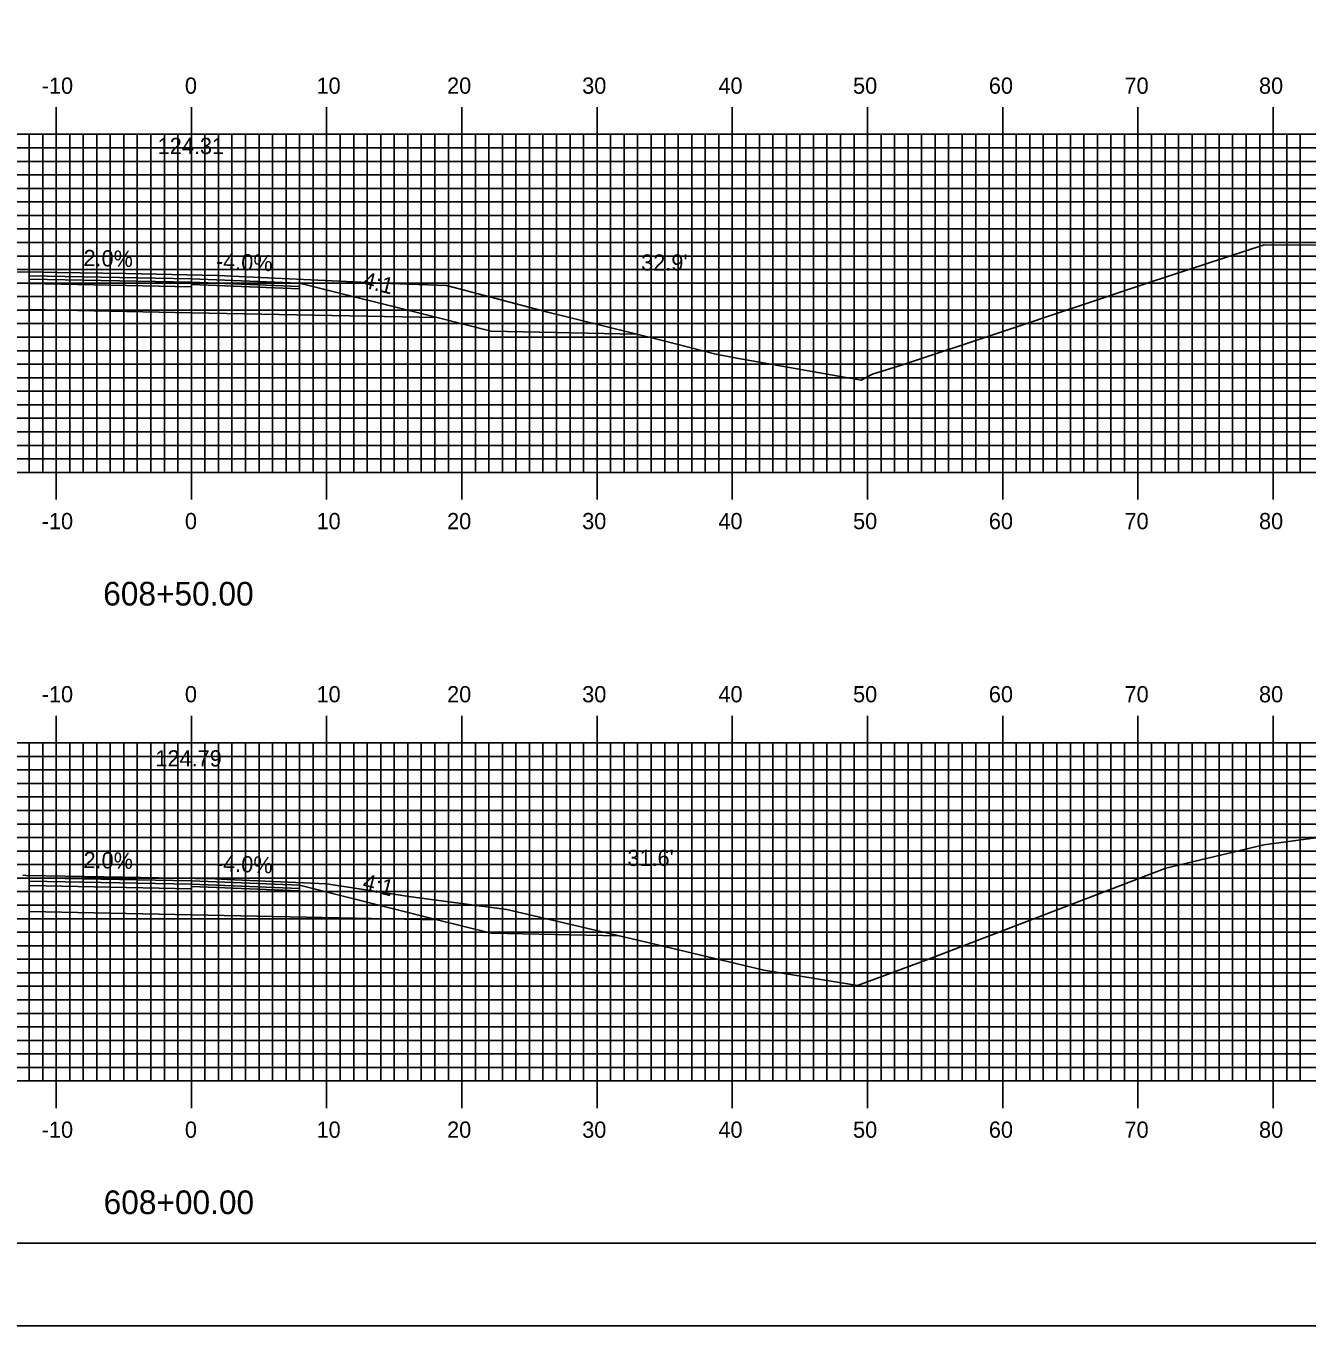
# Model space of a CAD drawing. Extents: x 842962 to 843305, y 363538 to 363758.
# Drawn here: x 843115.7 to 843210.4, y 363537.6 to 363633.7 of the extents above; entities that cross this region are included whole.
import ezdxf

# ---------------------------------------------------------------- set-up
doc = ezdxf.new("R2010")
doc.units = 0
for name, color, linetype in [('ANNOTATION', 7, 'Continuous'), ('BORDER', 7, 'Continuous'), ('D_Roadway_Centerline', 7, 'Continuous'), ('D_Roadway_Centerline_Text', 7, 'Continuous'), ('D_Roadway_Edge_Shoulder', 7, 'Continuous'), ('D_Roadway_Edge_TW', 7, 'Continuous'), ('D_Roadway_FinishedGrade', 7, 'Continuous'), ('D_Roadway_Pavement', 7, 'Continuous'), ('D_Roadway_SubGrade', 7, 'Continuous'), ('D_Text_Standard', 7, 'Continuous'), ('H_V ANNOTATION', 7, 'Continuous'), ('M_Roadway_Centerline', 7, 'Continuous'), ('MAJOR', 7, 'Continuous'), ('MINOR', 7, 'Continuous'), ('PLOT BOUNDARY', 7, 'Continuous'), ('S_Roadway_Centerline', 7, 'Continuous')]:
    doc.layers.add(name, color=color, linetype=linetype)

msp = doc.modelspace()

# ---------------------------------------------------------------- linework, layer by layer
at = {"layer": 'BORDER'}
msp.add_lwpolyline([(842978.311, 363543.721), (843298.311, 363543.721), (843298.311, 363753.721), (842978.311, 363753.721)], close=True, dxfattribs=at)
at = {"layer": 'D_Roadway_Centerline'}
msp.add_lwpolyline([(843115.911, 363570.752), (843127.911, 363570.512), (843135.911, 363570.192), (843146.085, 363567.648)], dxfattribs=at)
at = {"layer": 'D_Roadway_Edge_Shoulder'}
for p, q in [((843115.911, 363615.017), (843115.911, 363615.267)), ((843115.911, 363570.502), (843115.911, 363570.752))]:
    msp.add_line(p, q, dxfattribs=at)
for points in [[(843127.911, 363615.027), (843135.911, 363614.707), (843135.911, 363614.457), (843127.911, 363614.777)], [(843127.911, 363570.512), (843135.911, 363570.192), (843135.911, 363569.942), (843127.911, 363570.262)]]:
    msp.add_lwpolyline(points, close=True, dxfattribs=at)
at = {"layer": 'D_Roadway_Edge_TW'}
for points in [[(843115.911, 363615.267), (843127.911, 363615.027), (843127.911, 363614.777), (843115.911, 363615.017)], [(843115.911, 363570.752), (843127.911, 363570.512), (843127.911, 363570.262), (843115.911, 363570.502)]]:
    msp.add_lwpolyline(points, close=True, dxfattribs=at)
at = {"layer": 'D_Roadway_FinishedGrade'}
for points in [[(843146.085, 363612.163), (843150.085, 363611.163), (843160.782, 363610.949)], [(843146.085, 363567.648), (843150.085, 363566.648), (843159.503, 363566.46)]]:
    msp.add_lwpolyline(points, dxfattribs=at)
at = {"layer": 'D_Roadway_Pavement'}
for p, q in [((843115.911, 363614.683), (843115.911, 363615.017)), ((843115.911, 363570.168), (843115.911, 363570.502))]:
    msp.add_line(p, q, dxfattribs=at)
for points in [[(843115.911, 363615.017), (843127.911, 363614.777), (843127.911, 363614.443), (843115.911, 363614.683)], [(843127.911, 363614.777), (843135.911, 363614.457), (843135.911, 363614.29), (843127.911, 363614.61)], [(843115.911, 363570.502), (843127.911, 363570.262), (843127.911, 363569.928), (843115.911, 363570.168)], [(843127.911, 363570.262), (843135.911, 363569.942), (843135.911, 363569.775), (843127.911, 363570.095)]]:
    msp.add_lwpolyline(points, close=True, dxfattribs=at)
for points in [[(843127.911, 363614.777), (843127.911, 363614.443)], [(843127.911, 363614.777), (843127.911, 363614.443)], [(843127.911, 363570.262), (843127.911, 363569.928)], [(843127.911, 363570.262), (843127.911, 363569.928)]]:
    msp.add_lwpolyline(points, dxfattribs=at)
at = {"layer": 'D_Roadway_SubGrade'}
for p, q in [((843115.911, 363623.864), (843115.911, 363612.767)), ((843115.911, 363612.767), (843115.911, 363614.683)), ((843115.911, 363579.349), (843115.911, 363568.252)), ((843115.911, 363568.252), (843115.911, 363570.168))]:
    msp.add_line(p, q, dxfattribs=at)
for points in [[(843115.911, 363614.683), (843127.911, 363614.443), (843127.911, 363612.527), (843115.911, 363612.767)], [(843127.911, 363614.443), (843127.911, 363614.777), (843135.911, 363614.457), (843135.911, 363614.707), (843146.085, 363612.163), (843127.911, 363612.527)], [(843115.911, 363570.168), (843127.911, 363569.928), (843127.911, 363568.012), (843115.911, 363568.252)], [(843127.911, 363569.928), (843127.911, 363570.262), (843135.911, 363569.942), (843135.911, 363570.192), (843146.085, 363567.648), (843127.911, 363568.012)]]:
    msp.add_lwpolyline(points, close=True, dxfattribs=at)
at = {"layer": 'MAJOR'}
for p, q in [((843117.911, 363627.725), (843117.911, 363625.721)), ((843127.911, 363627.725), (843127.911, 363625.721)), ((843137.911, 363627.725), (843137.911, 363625.721)), ((843147.911, 363627.725), (843147.911, 363625.721)), ((843157.911, 363627.725), (843157.911, 363625.721)), ((843167.911, 363627.725), (843167.911, 363625.721)), ((843177.911, 363627.725), (843177.911, 363625.721)), ((843187.911, 363627.725), (843187.911, 363625.721)), ((843197.911, 363627.725), (843197.911, 363625.721)), ((843207.911, 363627.725), (843207.911, 363625.721)), ((842987.911, 363625.721), (843267.911, 363625.721)), ((842987.911, 363625.721), (843267.911, 363625.721)), ((843117.911, 363600.721), (843117.911, 363625.721)), ((843127.911, 363600.721), (843127.911, 363625.721)), ((843137.911, 363600.721), (843137.911, 363625.721)), ((843147.911, 363600.721), (843147.911, 363625.721)), ((843157.911, 363600.721), (843157.911, 363625.721)), ((843167.911, 363600.721), (843167.911, 363625.721)), ((843177.911, 363600.721), (843177.911, 363625.721)), ((843187.911, 363600.721), (843187.911, 363625.721)), ((843197.911, 363600.721), (843197.911, 363625.721)), ((843207.911, 363600.721), (843207.911, 363625.721)), ((842987.911, 363620.721), (843267.911, 363620.721)), ((842987.911, 363615.721), (843267.911, 363615.721)), ((842987.911, 363610.721), (843267.911, 363610.721)), ((842987.911, 363605.721), (843267.911, 363605.721)), ((842987.911, 363600.721), (843267.911, 363600.721)), ((842987.911, 363600.721), (843267.911, 363600.721)), ((843117.911, 363598.717), (843117.911, 363600.721)), ((843127.911, 363598.717), (843127.911, 363600.721)), ((843137.911, 363598.717), (843137.911, 363600.721)), ((843147.911, 363598.717), (843147.911, 363600.721)), ((843157.911, 363598.717), (843157.911, 363600.721)), ((843167.911, 363598.717), (843167.911, 363600.721)), ((843177.911, 363598.717), (843177.911, 363600.721)), ((843187.911, 363598.717), (843187.911, 363600.721)), ((843197.911, 363598.717), (843197.911, 363600.721)), ((843207.911, 363598.717), (843207.911, 363600.721)), ((843117.911, 363582.725), (843117.911, 363580.721)), ((843127.911, 363582.725), (843127.911, 363580.721)), ((843137.911, 363582.725), (843137.911, 363580.721)), ((843147.911, 363582.725), (843147.911, 363580.721)), ((843157.911, 363582.725), (843157.911, 363580.721)), ((843167.911, 363582.725), (843167.911, 363580.721)), ((843177.911, 363582.725), (843177.911, 363580.721)), ((843187.911, 363582.725), (843187.911, 363580.721)), ((843197.911, 363582.725), (843197.911, 363580.721)), ((843207.911, 363582.725), (843207.911, 363580.721)), ((842987.911, 363580.721), (843267.911, 363580.721)), ((842987.911, 363580.721), (843267.911, 363580.721)), ((843117.911, 363555.721), (843117.911, 363580.721)), ((843127.911, 363555.721), (843127.911, 363580.721)), ((843137.911, 363555.721), (843137.911, 363580.721)), ((843147.911, 363555.721), (843147.911, 363580.721)), ((843157.911, 363555.721), (843157.911, 363580.721)), ((843167.911, 363555.721), (843167.911, 363580.721)), ((843177.911, 363555.721), (843177.911, 363580.721)), ((843187.911, 363555.721), (843187.911, 363580.721)), ((843197.911, 363555.721), (843197.911, 363580.721)), ((843207.911, 363555.721), (843207.911, 363580.721)), ((842987.911, 363575.721), (843267.911, 363575.721)), ((842987.911, 363570.721), (843267.911, 363570.721)), ((842987.911, 363565.721), (843267.911, 363565.721)), ((842987.911, 363560.721), (843267.911, 363560.721)), ((842987.911, 363555.721), (843267.911, 363555.721)), ((842987.911, 363555.721), (843267.911, 363555.721)), ((843117.911, 363553.717), (843117.911, 363555.721)), ((843127.911, 363553.717), (843127.911, 363555.721)), ((843137.911, 363553.717), (843137.911, 363555.721)), ((843147.911, 363553.717), (843147.911, 363555.721)), ((843157.911, 363553.717), (843157.911, 363555.721)), ((843167.911, 363553.717), (843167.911, 363555.721)), ((843177.911, 363553.717), (843177.911, 363555.721)), ((843187.911, 363553.717), (843187.911, 363555.721)), ((843197.911, 363553.717), (843197.911, 363555.721)), ((843207.911, 363553.717), (843207.911, 363555.721))]:
    msp.add_line(p, q, dxfattribs=at)
at = {"layer": 'MINOR'}
for p, q in [((843115.911, 363600.721), (843115.911, 363625.721)), ((843116.911, 363600.721), (843116.911, 363625.721)), ((843118.911, 363600.721), (843118.911, 363625.721)), ((843119.911, 363600.721), (843119.911, 363625.721)), ((843120.911, 363600.721), (843120.911, 363625.721)), ((843121.911, 363600.721), (843121.911, 363625.721)), ((843122.911, 363600.721), (843122.911, 363625.721)), ((843123.911, 363600.721), (843123.911, 363625.721)), ((843124.911, 363600.721), (843124.911, 363625.721)), ((843125.911, 363600.721), (843125.911, 363625.721)), ((843126.911, 363600.721), (843126.911, 363625.721)), ((843128.911, 363600.721), (843128.911, 363625.721)), ((843129.911, 363600.721), (843129.911, 363625.721)), ((843130.911, 363600.721), (843130.911, 363625.721)), ((843131.911, 363600.721), (843131.911, 363625.721)), ((843132.911, 363600.721), (843132.911, 363625.721)), ((843133.911, 363600.721), (843133.911, 363625.721)), ((843134.911, 363600.721), (843134.911, 363625.721)), ((843135.911, 363600.721), (843135.911, 363625.721)), ((843136.911, 363600.721), (843136.911, 363625.721)), ((843138.911, 363600.721), (843138.911, 363625.721)), ((843139.911, 363600.721), (843139.911, 363625.721)), ((843140.911, 363600.721), (843140.911, 363625.721)), ((843141.911, 363600.721), (843141.911, 363625.721)), ((843142.911, 363600.721), (843142.911, 363625.721)), ((843143.911, 363600.721), (843143.911, 363625.721)), ((843144.911, 363600.721), (843144.911, 363625.721)), ((843145.911, 363600.721), (843145.911, 363625.721)), ((843146.911, 363600.721), (843146.911, 363625.721)), ((843148.911, 363600.721), (843148.911, 363625.721)), ((843149.911, 363600.721), (843149.911, 363625.721)), ((843150.911, 363600.721), (843150.911, 363625.721)), ((843151.911, 363600.721), (843151.911, 363625.721)), ((843152.911, 363600.721), (843152.911, 363625.721)), ((843153.911, 363600.721), (843153.911, 363625.721)), ((843154.911, 363600.721), (843154.911, 363625.721)), ((843155.911, 363600.721), (843155.911, 363625.721)), ((843156.911, 363600.721), (843156.911, 363625.721)), ((843158.911, 363600.721), (843158.911, 363625.721)), ((843159.911, 363600.721), (843159.911, 363625.721)), ((843160.911, 363600.721), (843160.911, 363625.721)), ((843161.911, 363600.721), (843161.911, 363625.721)), ((843162.911, 363600.721), (843162.911, 363625.721)), ((843163.911, 363600.721), (843163.911, 363625.721)), ((843164.911, 363600.721), (843164.911, 363625.721)), ((843165.911, 363600.721), (843165.911, 363625.721)), ((843166.911, 363600.721), (843166.911, 363625.721)), ((843168.911, 363600.721), (843168.911, 363625.721)), ((843169.911, 363600.721), (843169.911, 363625.721)), ((843170.911, 363600.721), (843170.911, 363625.721)), ((843171.911, 363600.721), (843171.911, 363625.721)), ((843172.911, 363600.721), (843172.911, 363625.721)), ((843173.911, 363600.721), (843173.911, 363625.721)), ((843174.911, 363600.721), (843174.911, 363625.721)), ((843175.911, 363600.721), (843175.911, 363625.721)), ((843176.911, 363600.721), (843176.911, 363625.721)), ((843178.911, 363600.721), (843178.911, 363625.721)), ((843179.911, 363600.721), (843179.911, 363625.721)), ((843180.911, 363600.721), (843180.911, 363625.721)), ((843181.911, 363600.721), (843181.911, 363625.721)), ((843182.911, 363600.721), (843182.911, 363625.721)), ((843183.911, 363600.721), (843183.911, 363625.721)), ((843184.911, 363600.721), (843184.911, 363625.721)), ((843185.911, 363600.721), (843185.911, 363625.721)), ((843186.911, 363600.721), (843186.911, 363625.721)), ((843188.911, 363600.721), (843188.911, 363625.721)), ((843189.911, 363600.721), (843189.911, 363625.721)), ((843190.911, 363600.721), (843190.911, 363625.721)), ((843191.911, 363600.721), (843191.911, 363625.721)), ((843192.911, 363600.721), (843192.911, 363625.721)), ((843193.911, 363600.721), (843193.911, 363625.721)), ((843194.911, 363600.721), (843194.911, 363625.721)), ((843195.911, 363600.721), (843195.911, 363625.721)), ((843196.911, 363600.721), (843196.911, 363625.721)), ((843198.911, 363600.721), (843198.911, 363625.721)), ((843199.911, 363600.721), (843199.911, 363625.721)), ((843200.911, 363600.721), (843200.911, 363625.721)), ((843201.911, 363600.721), (843201.911, 363625.721)), ((843202.911, 363600.721), (843202.911, 363625.721)), ((843203.911, 363600.721), (843203.911, 363625.721)), ((843204.911, 363600.721), (843204.911, 363625.721)), ((843205.911, 363600.721), (843205.911, 363625.721)), ((843206.911, 363600.721), (843206.911, 363625.721)), ((843208.911, 363600.721), (843208.911, 363625.721)), ((843209.911, 363600.721), (843209.911, 363625.721)), ((842987.911, 363624.721), (843267.911, 363624.721)), ((842987.911, 363623.721), (843267.911, 363623.721)), ((842987.911, 363622.721), (843267.911, 363622.721)), ((842987.911, 363621.721), (843267.911, 363621.721)), ((842987.911, 363619.721), (843267.911, 363619.721)), ((842987.911, 363618.721), (843267.911, 363618.721)), ((842987.911, 363617.721), (843267.911, 363617.721)), ((842987.911, 363616.721), (843267.911, 363616.721)), ((842987.911, 363614.721), (843267.911, 363614.721)), ((842987.911, 363613.721), (843267.911, 363613.721)), ((842987.911, 363612.721), (843267.911, 363612.721)), ((842987.911, 363611.721), (843267.911, 363611.721)), ((842987.911, 363609.721), (843267.911, 363609.721)), ((842987.911, 363608.721), (843267.911, 363608.721)), ((842987.911, 363607.721), (843267.911, 363607.721)), ((842987.911, 363606.721), (843267.911, 363606.721)), ((842987.911, 363604.721), (843267.911, 363604.721)), ((842987.911, 363603.721), (843267.911, 363603.721)), ((842987.911, 363602.721), (843267.911, 363602.721)), ((842987.911, 363601.721), (843267.911, 363601.721)), ((843115.911, 363555.721), (843115.911, 363580.721)), ((843116.911, 363555.721), (843116.911, 363580.721)), ((843118.911, 363555.721), (843118.911, 363580.721)), ((843119.911, 363555.721), (843119.911, 363580.721)), ((843120.911, 363555.721), (843120.911, 363580.721)), ((843121.911, 363555.721), (843121.911, 363580.721)), ((843122.911, 363555.721), (843122.911, 363580.721)), ((843123.911, 363555.721), (843123.911, 363580.721)), ((843124.911, 363555.721), (843124.911, 363580.721)), ((843125.911, 363555.721), (843125.911, 363580.721)), ((843126.911, 363555.721), (843126.911, 363580.721)), ((843128.911, 363555.721), (843128.911, 363580.721)), ((843129.911, 363555.721), (843129.911, 363580.721)), ((843130.911, 363555.721), (843130.911, 363580.721)), ((843131.911, 363555.721), (843131.911, 363580.721)), ((843132.911, 363555.721), (843132.911, 363580.721)), ((843133.911, 363555.721), (843133.911, 363580.721)), ((843134.911, 363555.721), (843134.911, 363580.721)), ((843135.911, 363555.721), (843135.911, 363580.721)), ((843136.911, 363555.721), (843136.911, 363580.721)), ((843138.911, 363555.721), (843138.911, 363580.721)), ((843139.911, 363555.721), (843139.911, 363580.721)), ((843140.911, 363555.721), (843140.911, 363580.721)), ((843141.911, 363555.721), (843141.911, 363580.721)), ((843142.911, 363555.721), (843142.911, 363580.721)), ((843143.911, 363555.721), (843143.911, 363580.721)), ((843144.911, 363555.721), (843144.911, 363580.721)), ((843145.911, 363555.721), (843145.911, 363580.721)), ((843146.911, 363555.721), (843146.911, 363580.721)), ((843148.911, 363555.721), (843148.911, 363580.721)), ((843149.911, 363555.721), (843149.911, 363580.721)), ((843150.911, 363555.721), (843150.911, 363580.721)), ((843151.911, 363555.721), (843151.911, 363580.721)), ((843152.911, 363555.721), (843152.911, 363580.721)), ((843153.911, 363555.721), (843153.911, 363580.721)), ((843154.911, 363555.721), (843154.911, 363580.721)), ((843155.911, 363555.721), (843155.911, 363580.721)), ((843156.911, 363555.721), (843156.911, 363580.721)), ((843158.911, 363555.721), (843158.911, 363580.721)), ((843159.911, 363555.721), (843159.911, 363580.721)), ((843160.911, 363555.721), (843160.911, 363580.721)), ((843161.911, 363555.721), (843161.911, 363580.721)), ((843162.911, 363555.721), (843162.911, 363580.721)), ((843163.911, 363555.721), (843163.911, 363580.721)), ((843164.911, 363555.721), (843164.911, 363580.721)), ((843165.911, 363555.721), (843165.911, 363580.721)), ((843166.911, 363555.721), (843166.911, 363580.721)), ((843168.911, 363555.721), (843168.911, 363580.721)), ((843169.911, 363555.721), (843169.911, 363580.721)), ((843170.911, 363555.721), (843170.911, 363580.721)), ((843171.911, 363555.721), (843171.911, 363580.721)), ((843172.911, 363555.721), (843172.911, 363580.721)), ((843173.911, 363555.721), (843173.911, 363580.721)), ((843174.911, 363555.721), (843174.911, 363580.721)), ((843175.911, 363555.721), (843175.911, 363580.721)), ((843176.911, 363555.721), (843176.911, 363580.721)), ((843178.911, 363555.721), (843178.911, 363580.721)), ((843179.911, 363555.721), (843179.911, 363580.721)), ((843180.911, 363555.721), (843180.911, 363580.721)), ((843181.911, 363555.721), (843181.911, 363580.721)), ((843182.911, 363555.721), (843182.911, 363580.721)), ((843183.911, 363555.721), (843183.911, 363580.721)), ((843184.911, 363555.721), (843184.911, 363580.721)), ((843185.911, 363555.721), (843185.911, 363580.721)), ((843186.911, 363555.721), (843186.911, 363580.721)), ((843188.911, 363555.721), (843188.911, 363580.721)), ((843189.911, 363555.721), (843189.911, 363580.721)), ((843190.911, 363555.721), (843190.911, 363580.721)), ((843191.911, 363555.721), (843191.911, 363580.721)), ((843192.911, 363555.721), (843192.911, 363580.721)), ((843193.911, 363555.721), (843193.911, 363580.721)), ((843194.911, 363555.721), (843194.911, 363580.721)), ((843195.911, 363555.721), (843195.911, 363580.721)), ((843196.911, 363555.721), (843196.911, 363580.721)), ((843198.911, 363555.721), (843198.911, 363580.721)), ((843199.911, 363555.721), (843199.911, 363580.721)), ((843200.911, 363555.721), (843200.911, 363580.721)), ((843201.911, 363555.721), (843201.911, 363580.721)), ((843202.911, 363555.721), (843202.911, 363580.721)), ((843203.911, 363555.721), (843203.911, 363580.721)), ((843204.911, 363555.721), (843204.911, 363580.721)), ((843205.911, 363555.721), (843205.911, 363580.721)), ((843206.911, 363555.721), (843206.911, 363580.721)), ((843208.911, 363555.721), (843208.911, 363580.721)), ((843209.911, 363555.721), (843209.911, 363580.721)), ((842987.911, 363579.721), (843267.911, 363579.721)), ((842987.911, 363578.721), (843267.911, 363578.721)), ((842987.911, 363577.721), (843267.911, 363577.721)), ((842987.911, 363576.721), (843267.911, 363576.721)), ((842987.911, 363574.721), (843267.911, 363574.721)), ((842987.911, 363573.721), (843267.911, 363573.721)), ((842987.911, 363572.721), (843267.911, 363572.721)), ((842987.911, 363571.721), (843267.911, 363571.721)), ((842987.911, 363569.721), (843267.911, 363569.721)), ((842987.911, 363568.721), (843267.911, 363568.721)), ((842987.911, 363567.721), (843267.911, 363567.721)), ((842987.911, 363566.721), (843267.911, 363566.721)), ((842987.911, 363564.721), (843267.911, 363564.721)), ((842987.911, 363563.721), (843267.911, 363563.721)), ((842987.911, 363562.721), (843267.911, 363562.721)), ((842987.911, 363561.721), (843267.911, 363561.721)), ((842987.911, 363559.721), (843267.911, 363559.721)), ((842987.911, 363558.721), (843267.911, 363558.721)), ((842987.911, 363557.721), (843267.911, 363557.721)), ((842987.911, 363556.721), (843267.911, 363556.721))]:
    msp.add_line(p, q, dxfattribs=at)
at = {"layer": 'PLOT BOUNDARY'}
msp.add_lwpolyline([(842962.124, 363537.603), (843302.124, 363537.603), (843302.124, 363757.603), (842962.124, 363757.603)], close=True, dxfattribs=at)
at = {"layer": 'S_Roadway_Centerline'}
for points in [[(843107.74, 363615.416), (843115.927, 363615.541), (843117.976, 363615.494), (843123.068, 363615.424), (843129.843, 363615.286), (843140.989, 363614.773), (843142.642, 363614.698), (843146.77, 363614.551), (843154.277, 363612.568), (843162.837, 363610.438), (843166.582, 363609.479), (843168.096, 363609.196), (843177.446, 363607.539), (843178.274, 363607.974), (843180.495, 363608.669), (843187.764, 363611.102), (843198.743, 363614.765), (843207.25, 363617.544), (843219.101, 363617.532)], [(843115.433, 363570.927), (843115.701, 363570.924), (843121.46, 363570.816), (843128.21, 363570.687), (843129.673, 363570.664), (843130.549, 363570.627), (843131.088, 363570.606), (843137.889, 363570.292), (843144.162, 363569.328), (843151.248, 363568.391), (843161.352, 363566.027), (843170.244, 363563.905), (843176.735, 363562.851), (843177.162, 363562.79), (843182.288, 363564.676), (843199.964, 363571.467), (843207.214, 363573.172), (843212.898, 363573.941)]]:
    msp.add_lwpolyline(points, dxfattribs=at)

# ---------------------------------------------------------------- texts
at = {"layer": 'ANNOTATION'}
for s, rotation, p in [('2.0%', 358.85424, (843119.918, 363615.987)), ('-4.0%', 357.70939, (843129.703, 363615.757)), ('4:1', 345.96376, (843140.504, 363614.42)), ('2.0%', 358.85424, (843119.918, 363571.472)), ('-4.0%', 357.70939, (843129.703, 363571.242)), ('4:1', 345.96376, (843140.504, 363569.905))]:
    msp.add_text(s, height=1.2, rotation=rotation, dxfattribs=at).set_placement(p)
at = {"layer": 'D_Roadway_Centerline_Text'}
for s, p in [('124.31', (843125.418, 363624.262)), ('124.79', (843125.246, 363578.975))]:
    msp.add_text(s, height=1.2, dxfattribs=at).set_placement(p)
at = {"layer": 'D_Text_Standard'}
for s, p in [("32.9'", (843161.173, 363615.642)), ("31.6'", (843160.151, 363571.618))]:
    msp.add_text(s, height=1.2, dxfattribs=at).set_placement(p)
at = {"layer": 'H_V ANNOTATION'}
for s, height, p in [('-10', 1.2, (843116.841, 363628.721)), ('0', 1.2, (843127.429, 363628.721)), ('10', 1.2, (843137.162, 363628.721)), ('20', 1.2, (843146.819, 363628.721)), ('30', 1.2, (843156.809, 363628.721)), ('40', 1.2, (843166.883, 363628.721)), ('50', 1.2, (843176.841, 363628.721)), ('60', 1.2, (843186.883, 363628.721)), ('70', 1.2, (843196.915, 363628.721)), ('80', 1.2, (843206.862, 363628.721)), ('-10', 1.2, (843116.841, 363596.521)), ('0', 1.2, (843127.429, 363596.521)), ('10', 1.2, (843137.162, 363596.521)), ('20', 1.2, (843146.819, 363596.521)), ('30', 1.2, (843156.809, 363596.521)), ('40', 1.2, (843166.883, 363596.521)), ('50', 1.2, (843176.841, 363596.521)), ('60', 1.2, (843186.883, 363596.521)), ('70', 1.2, (843196.915, 363596.521)), ('80', 1.2, (843206.862, 363596.521)), ('608+50.00', 1.75, (843121.388, 363590.877)), ('-10', 1.2, (843116.841, 363583.721)), ('0', 1.2, (843127.429, 363583.721)), ('10', 1.2, (843137.162, 363583.721)), ('20', 1.2, (843146.819, 363583.721)), ('30', 1.2, (843156.809, 363583.721)), ('40', 1.2, (843166.883, 363583.721)), ('50', 1.2, (843176.841, 363583.721)), ('60', 1.2, (843186.883, 363583.721)), ('70', 1.2, (843196.915, 363583.721)), ('80', 1.2, (843206.862, 363583.721)), ('-10', 1.2, (843116.841, 363551.521)), ('0', 1.2, (843127.429, 363551.521)), ('10', 1.2, (843137.162, 363551.521)), ('20', 1.2, (843146.819, 363551.521)), ('30', 1.2, (843156.809, 363551.521)), ('40', 1.2, (843166.883, 363551.521)), ('50', 1.2, (843176.841, 363551.521)), ('60', 1.2, (843186.883, 363551.521)), ('70', 1.2, (843196.915, 363551.521)), ('80', 1.2, (843206.862, 363551.521)), ('608+00.00', 1.75, (843121.419, 363545.877))]:
    msp.add_text(s, height=height, dxfattribs=at).set_placement(p)
at = {"layer": 'M_Roadway_Centerline'}
for s, p in [('C', (843115.922, 363615.541)), ('L', (843115.927, 363615.534))]:
    msp.add_text(s, height=0.0146, dxfattribs=at).set_placement(p)

doc.saveas('drawing.dxf')
